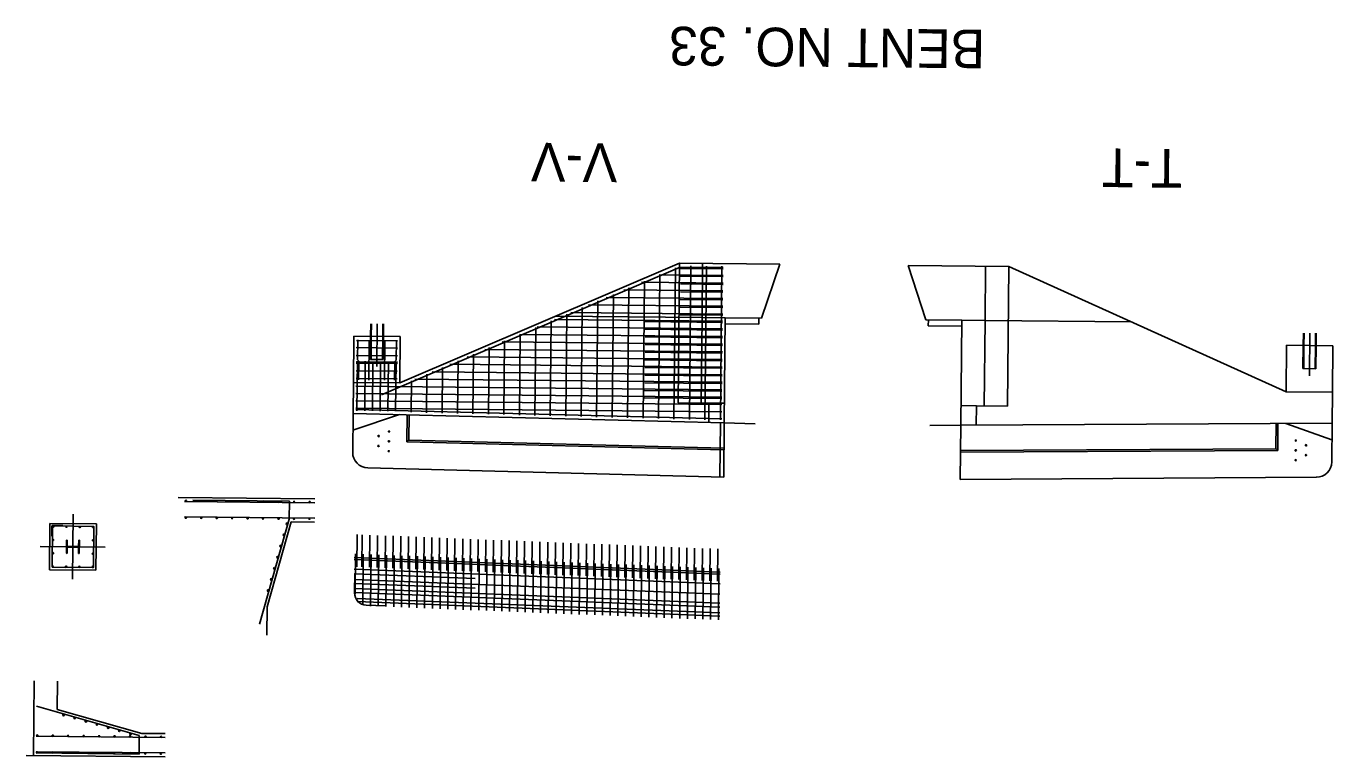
# Model space of a CAD drawing. Extents: x 631918 to 632319, y 373181 to 373282.
# Drawn here: x 632021.2 to 632105.7, y 373204.7 to 373251.9 of the extents above; entities that cross this region are included whole.
import ezdxf

# ---------------------------------------------------------------- set-up
doc = ezdxf.new("R2010")
doc.units = 0
for name, color, linetype in [('B_Boring', 7, 'Continuous'), ('BD-EXIST-OSB', 7, 'Continuous'), ('BD-LEGEND', 7, 'Continuous'), ('BD-PROP-COSS', 7, 'Continuous'), ('BD-REMOVE', 7, 'Continuous'), ('R_Border_Scale', 7, 'Continuous'), ('R_Road Edge of Travel', 7, 'Continuous'), ('R_Shade Removal', 7, 'Continuous'), ('R_Wall', 7, 'Continuous')]:
    doc.layers.add(name, color=color, linetype=linetype)

msp = doc.modelspace()

# ---------------------------------------------------------------- linework, layer by layer
at = {"layer": 'B_Boring'}
for p, q in [((632084.738, 373236.403), (632084.649, 373227.381)), ((632083.204, 373232.918), (632083.149, 373227.396)), ((632045.824, 373225.073), (632045.841, 373226.823)), ((632045.95, 373225.194), (632045.966, 373226.821)), ((632082.636, 373226.151), (632082.649, 373227.401)), ((632082.649, 373227.401), (632084.649, 373227.381)), ((632105.628, 373225.2), (632102.639, 373226.266)), ((632045.95, 373225.194), (632045.824, 373225.073)), ((632066.32, 373224.547), (632045.824, 373225.062)), ((632066.321, 373224.67), (632045.95, 373225.183))]:
    msp.add_line(p, q, dxfattribs=at)
at = {"layer": 'BD-EXIST-OSB'}
for p, q in [((632023.817, 373218.717), (632023.809, 373217.863)), ((632023.864, 373218.716), (632023.817, 373218.717)), ((632023.856, 373217.862), (632023.86, 373218.266)), ((632023.86, 373218.313), (632023.864, 373218.716)), ((632023.86, 373218.313), (632024.23, 373218.309)), ((632023.86, 373218.266), (632024.229, 373218.262)), ((632024.599, 373218.259), (632024.229, 373218.262)), ((632024.6, 373218.305), (632024.23, 373218.309)), ((632024.595, 373217.855), (632024.599, 373218.259)), ((632024.6, 373218.305), (632024.604, 373218.709)), ((632024.604, 373218.709), (632024.651, 373218.709)), ((632024.651, 373218.709), (632024.642, 373217.854)), ((632023.856, 373217.862), (632023.809, 373217.863)), ((632024.595, 373217.855), (632024.642, 373217.854))]:
    msp.add_line(p, q, dxfattribs=at)
at = {"layer": 'BD-LEGEND'}
for p, q in [((632039.871, 373221.38), (632031.026, 373221.468)), ((632036.79, 373214.411), (632038.345, 373219.895)), ((632039.856, 373219.88), (632038.345, 373219.895)), ((632022.715, 373216.801), (632022.745, 373219.801)), ((632025.744, 373219.771), (632022.745, 373219.801)), ((632025.744, 373219.771), (632025.715, 373216.771)), ((632025.715, 373216.771), (632022.715, 373216.801)), ((632036.79, 373214.411), (632036.772, 373212.58)), ((632021.723, 373209.619), (632021.675, 373204.789)), ((632023.205, 373207.774), (632023.223, 373209.604)), ((632023.205, 373207.774), (632028.689, 373206.219)), ((632030.201, 373206.204), (632028.689, 373206.219)), ((632030.186, 373204.704), (632021.204, 373204.793))]:
    msp.add_line(p, q, dxfattribs=at)
at = {"layer": 'BD-PROP-COSS'}
for p, q in [((632063.49, 373236.364), (632044.181, 373228.106)), ((632062.182, 373235.895), (632062.09, 373226.573)), ((632063.187, 373236.325), (632063.089, 373226.547)), ((632066.27, 373236.336), (632063.49, 373236.364)), ((632066.269, 373236.253), (632063.52, 373236.28)), ((632063.52, 373236.28), (632063.603, 373236.279)), ((632064.188, 373236.44), (632064.089, 373226.506)), ((632065.188, 373236.43), (632065.089, 373226.496)), ((632066.188, 373236.42), (632066.089, 373226.486)), ((632066.26, 373235.336), (632060.997, 373235.389)), ((632061.178, 373235.466), (632061.09, 373226.598)), ((632066.265, 373235.836), (632062.14, 373235.877)), ((632066.259, 373235.253), (632063.51, 373235.28)), ((632066.264, 373235.753), (632063.515, 373235.78)), ((632066.25, 373234.336), (632058.712, 373234.411)), ((632059.169, 373234.607), (632059.09, 373226.65)), ((632066.255, 373234.836), (632059.855, 373234.9)), ((632060.174, 373235.036), (632060.09, 373226.624)), ((632066.249, 373234.253), (632063.5, 373234.28)), ((632066.254, 373234.753), (632063.505, 373234.78)), ((632066.24, 373233.336), (632056.427, 373233.434)), ((632057.161, 373233.748), (632057.091, 373226.701)), ((632066.245, 373233.836), (632057.57, 373233.923)), ((632058.165, 373234.177), (632058.09, 373226.675)), ((632066.245, 373233.753), (632063.495, 373233.78)), ((632055.152, 373232.889), (632055.091, 373226.752)), ((632055.371, 373232.982), (632066.236, 373232.874)), ((632056.156, 373233.318), (632056.091, 373226.727)), ((632066.235, 373232.791), (632061.235, 373232.841)), ((632066.24, 373233.253), (632063.49, 373233.28)), ((632042.626, 373230.368), (632042.639, 373231.66)), ((632053.143, 373232.03), (632053.091, 373226.804)), ((632053.112, 373232.016), (632066.226, 373231.886)), ((632054.148, 373232.459), (632054.091, 373226.778)), ((632054.242, 373232.499), (632066.231, 373232.38)), ((632066.225, 373231.802), (632061.225, 373231.852)), ((632066.23, 373232.297), (632061.23, 373232.346)), ((632045.217, 373231.134), (632042.551, 373231.161)), ((632045.222, 373231.593), (632042.555, 373231.619)), ((632043.363, 373229.069), (632043.389, 373231.652)), ((632044.363, 373229.059), (632044.389, 373231.642)), ((632045.126, 373230.343), (632045.139, 373231.635)), ((632050.853, 373231.05), (632066.216, 373230.897)), ((632051.135, 373231.17), (632051.092, 373226.855)), ((632051.982, 373231.533), (632066.221, 373231.391)), ((632052.139, 373231.6), (632052.092, 373226.829)), ((632066.215, 373230.814), (632061.216, 373230.863)), ((632066.22, 373231.308), (632061.22, 373231.358)), ((632045.208, 373230.134), (632042.541, 373230.161)), ((632045.208, 373230.218), (632042.542, 373230.244)), ((632045.212, 373230.634), (632042.546, 373230.661)), ((632042.594, 373227.077), (632042.626, 373230.285)), ((632042.626, 373230.368), (632042.709, 373230.284)), ((632042.697, 373229.076), (632042.709, 373230.284)), ((632043.094, 373227.072), (632043.126, 373230.28)), ((632043.594, 373227.067), (632043.625, 373230.275)), ((632044.094, 373227.062), (632044.125, 373230.27)), ((632044.594, 373227.057), (632044.625, 373230.265)), ((632045.03, 373229.053), (632045.042, 373230.261)), ((632045.126, 373230.343), (632045.042, 373230.261)), ((632045.094, 373227.052), (632045.125, 373230.26)), ((632048.594, 373230.084), (632066.206, 373229.908)), ((632049.126, 373230.311), (632049.092, 373226.906)), ((632049.723, 373230.567), (632066.211, 373230.403)), ((632050.13, 373230.741), (632050.092, 373226.881)), ((632066.21, 373230.319), (632061.211, 373230.369)), ((632045.198, 373229.134), (632042.531, 373229.161)), ((632045.203, 373229.634), (632042.536, 373229.661)), ((632047.117, 373229.452), (632047.093, 373226.957)), ((632047.464, 373229.6), (632066.201, 373229.414)), ((632048.122, 373229.882), (632048.092, 373226.932)), ((632066.201, 373229.331), (632061.201, 373229.381)), ((632066.205, 373229.825), (632061.206, 373229.875)), ((632042.526, 373228.661), (632066.192, 373228.426)), ((632046.113, 373229.023), (632046.093, 373226.983)), ((632046.334, 373229.117), (632066.196, 373228.92)), ((632066.191, 373228.342), (632061.191, 373228.392)), ((632066.196, 373228.837), (632061.196, 373228.886)), ((632042.517, 373227.723), (632066.182, 373227.488)), ((632042.521, 373228.192), (632066.187, 373227.957)), ((632066.186, 373227.874), (632061.186, 373227.923)), ((632066.173, 373226.551), (632042.511, 373227.158)), ((632042.512, 373227.255), (632066.178, 373227.019)), ((632039.869, 373221.13), (632031.451, 373221.214)), ((632038.231, 373221.23), (632031.981, 373221.292)), ((632038.219, 373220.063), (632038.231, 373221.23)), ((632039.859, 373220.13), (632031.441, 373220.214)), ((632036.297, 373213.282), (632038.219, 373220.063)), ((632022.861, 373218.966), (632022.868, 373219.633)), ((632025.576, 373219.606), (632022.868, 373219.633)), ((632022.883, 373216.966), (632022.91, 373219.674)), ((632023.577, 373219.667), (632022.91, 373219.674)), ((632025.576, 373219.606), (632025.55, 373216.939)), ((632042.577, 373216.994), (632042.597, 373219.077)), ((632042.931, 373219.064), (632042.91, 373216.98)), ((632043.43, 373219.044), (632043.41, 373216.96)), ((632043.93, 373219.024), (632043.91, 373216.94)), ((632044.43, 373219.004), (632044.409, 373216.921)), ((632044.93, 373218.984), (632044.909, 373216.901)), ((632045.43, 373218.964), (632045.409, 373216.881)), ((632045.93, 373218.944), (632045.909, 373216.861)), ((632046.429, 373218.924), (632046.409, 373216.841)), ((632046.929, 373218.904), (632046.909, 373216.821)), ((632047.429, 373218.884), (632047.408, 373216.801)), ((632047.929, 373218.864), (632047.908, 373216.781)), ((632048.429, 373218.844), (632048.408, 373216.761)), ((632048.929, 373218.824), (632048.908, 373216.741)), ((632049.428, 373218.804), (632049.408, 373216.721)), ((632049.928, 373218.784), (632049.908, 373216.701)), ((632050.428, 373218.764), (632050.407, 373216.681)), ((632050.928, 373218.744), (632050.907, 373216.661)), ((632051.428, 373218.724), (632051.407, 373216.641)), ((632051.928, 373218.704), (632051.907, 373216.621)), ((632052.427, 373218.684), (632052.407, 373216.601)), ((632052.927, 373218.664), (632052.906, 373216.581)), ((632053.427, 373218.644), (632053.406, 373216.561)), ((632053.927, 373218.624), (632053.906, 373216.541)), ((632054.427, 373218.604), (632054.406, 373216.521)), ((632054.926, 373218.584), (632054.906, 373216.501)), ((632055.426, 373218.564), (632055.406, 373216.481)), ((632055.926, 373218.544), (632055.905, 373216.461)), ((632056.426, 373218.524), (632056.405, 373216.441)), ((632056.926, 373218.504), (632056.905, 373216.421)), ((632057.426, 373218.485), (632057.405, 373216.401)), ((632057.925, 373218.465), (632057.905, 373216.381)), ((632058.425, 373218.445), (632058.405, 373216.361)), ((632058.925, 373218.425), (632058.904, 373216.341)), ((632059.425, 373218.405), (632059.404, 373216.321)), ((632059.925, 373218.385), (632059.904, 373216.301)), ((632060.425, 373218.365), (632060.404, 373216.281)), ((632060.924, 373218.345), (632060.904, 373216.262)), ((632061.424, 373218.325), (632061.404, 373216.242)), ((632061.924, 373218.305), (632061.903, 373216.222)), ((632062.424, 373218.285), (632062.403, 373216.202)), ((632062.924, 373218.265), (632062.903, 373216.182)), ((632063.424, 373218.245), (632063.403, 373216.162)), ((632063.923, 373218.225), (632063.903, 373216.142)), ((632064.423, 373218.205), (632064.402, 373216.122)), ((632064.923, 373218.185), (632064.902, 373216.102)), ((632065.423, 373218.165), (632065.402, 373216.082)), ((632065.923, 373218.145), (632065.902, 373216.062)), ((632066.073, 373216.513), (632042.415, 373217.459)), ((632066.074, 373216.638), (632042.416, 373217.584)), ((632042.476, 373215.247), (632042.502, 373217.83)), ((632043.002, 373217.81), (632042.969, 373214.561)), ((632043.501, 373217.79), (632043.468, 373214.457)), ((632044.001, 373217.77), (632043.968, 373214.437)), ((632044.501, 373217.75), (632044.468, 373214.417)), ((632045.001, 373217.731), (632044.968, 373214.397)), ((632045.501, 373217.711), (632045.468, 373214.377)), ((632046, 373217.691), (632045.967, 373214.357)), ((632046.5, 373217.671), (632046.467, 373214.337)), ((632047, 373217.651), (632046.967, 373214.317)), ((632047.5, 373217.631), (632047.467, 373214.297)), ((632048, 373217.611), (632047.967, 373214.278)), ((632048.5, 373217.591), (632048.466, 373214.258)), ((632048.999, 373217.571), (632048.966, 373214.238)), ((632049.499, 373217.551), (632049.466, 373214.218)), ((632049.999, 373217.531), (632049.966, 373214.198)), ((632050.499, 373217.511), (632050.466, 373214.178)), ((632050.999, 373217.491), (632050.966, 373214.158)), ((632051.499, 373217.471), (632051.465, 373214.138)), ((632051.998, 373217.451), (632051.965, 373214.118)), ((632052.498, 373217.431), (632052.465, 373214.098)), ((632052.998, 373217.411), (632052.965, 373214.078)), ((632053.498, 373217.391), (632053.465, 373214.058)), ((632053.998, 373217.371), (632053.965, 373214.038)), ((632054.498, 373217.351), (632054.464, 373214.018)), ((632054.997, 373217.331), (632054.964, 373213.998)), ((632055.497, 373217.311), (632055.464, 373213.978)), ((632025.55, 373216.939), (632022.883, 373216.966)), ((632050.236, 373216.229), (632042.406, 373216.542)), ((632066.067, 373215.888), (632042.408, 373216.834)), ((632042.435, 373215.309), (632042.447, 373216.559)), ((632055.997, 373217.291), (632055.964, 373213.958)), ((632056.497, 373217.271), (632056.464, 373213.938)), ((632056.997, 373217.251), (632056.964, 373213.918)), ((632057.497, 373217.231), (632057.463, 373213.898)), ((632057.996, 373217.211), (632057.963, 373213.878)), ((632058.496, 373217.191), (632058.463, 373213.858)), ((632058.996, 373217.171), (632058.963, 373213.838)), ((632059.496, 373217.151), (632059.463, 373213.818)), ((632059.996, 373217.131), (632059.962, 373213.798)), ((632060.495, 373217.111), (632060.462, 373213.778)), ((632060.995, 373217.091), (632060.962, 373213.758)), ((632061.495, 373217.072), (632061.462, 373213.738)), ((632061.995, 373217.052), (632061.962, 373213.718)), ((632062.495, 373217.032), (632062.462, 373213.698)), ((632062.995, 373217.012), (632062.961, 373213.678)), ((632063.494, 373216.992), (632063.461, 373213.658)), ((632063.994, 373216.972), (632063.961, 373213.638)), ((632064.494, 373216.952), (632064.461, 373213.619)), ((632064.994, 373216.932), (632064.961, 373213.599)), ((632065.494, 373216.912), (632065.461, 373213.579)), ((632065.994, 373216.892), (632065.96, 373213.559)), ((632050.23, 373215.604), (632042.399, 373215.917)), ((632066.06, 373215.222), (632042.402, 373216.167)), ((632066.052, 373214.389), (632042.394, 373215.334)), ((632066.054, 373214.639), (632042.396, 373215.584)), ((632066.048, 373214.014), (632042.617, 373214.95)), ((632066.046, 373213.805), (632042.609, 373214.742)), ((632044.444, 373214.46), (632043.195, 373214.51)), ((632021.873, 373207.978), (632028.521, 373206.093)), ((632030.199, 373205.954), (632021.854, 373206.037)), ((632028.521, 373206.093), (632028.509, 373204.887)), ((632028.509, 373204.887), (632021.843, 373204.954)), ((632030.189, 373204.954), (632021.844, 373205.037))]:
    msp.add_line(p, q, dxfattribs=at)
for centre, radius in [((632031.535, 373221.255), 0.0417), ((632032.535, 373221.245), 0.0417), ((632033.535, 373221.235), 0.0417), ((632034.535, 373221.225), 0.0417), ((632035.535, 373221.215), 0.0417), ((632036.535, 373221.205), 0.0417), ((632037.535, 373221.195), 0.0417), ((632038.535, 373221.185), 0.0417), ((632039.535, 373221.175), 0.0417), ((632031.524, 373220.172), 0.0417), ((632032.524, 373220.162), 0.0417), ((632033.524, 373220.152), 0.0417), ((632034.524, 373220.142), 0.0417), ((632035.524, 373220.132), 0.0417), ((632036.524, 373220.122), 0.0417), ((632037.524, 373220.112), 0.0417), ((632038.524, 373220.102), 0.0417), ((632039.524, 373220.092), 0.0417), ((632022.951, 373219.59), 0.0417), ((632023.812, 373219.582), 0.0417), ((632024.673, 373219.573), 0.0417), ((632025.534, 373219.564), 0.0417), ((632037.875, 373219.052), 0.0556), ((632038.078, 373219.771), 0.0556), ((632022.942, 373218.729), 0.0417), ((632025.526, 373218.703), 0.0417), ((632037.671, 373218.333), 0.0556), ((632022.934, 373217.868), 0.0417), ((632025.517, 373217.842), 0.0417), ((632037.467, 373217.613), 0.0556), ((632022.925, 373217.007), 0.0417), ((632023.786, 373216.998), 0.0417), ((632024.647, 373216.99), 0.0417), ((632025.508, 373216.981), 0.0417), ((632037.263, 373216.894), 0.0556), ((632037.059, 373216.174), 0.0556), ((632036.855, 373215.455), 0.0556), ((632023.623, 373207.418), 0.0556), ((632024.345, 373207.214), 0.0556), ((632025.067, 373207.009), 0.0556), ((632025.789, 373206.805), 0.0556), ((632026.511, 373206.6), 0.0556), ((632027.233, 373206.395), 0.0556), ((632021.923, 373206.078), 0.0417), ((632022.923, 373206.068), 0.0417), ((632023.923, 373206.058), 0.0417), ((632024.923, 373206.048), 0.0417), ((632025.923, 373206.038), 0.0417), ((632026.923, 373206.028), 0.0417), ((632027.923, 373206.018), 0.0417), ((632027.955, 373206.191), 0.0556), ((632028.923, 373206.008), 0.0417), ((632029.923, 373205.998), 0.0417), ((632021.912, 373204.995), 0.0417), ((632022.912, 373204.985), 0.0417), ((632023.912, 373204.975), 0.0417), ((632024.912, 373204.965), 0.0417), ((632025.912, 373204.955), 0.0417), ((632026.912, 373204.945), 0.0417), ((632027.912, 373204.935), 0.0417), ((632028.912, 373204.925), 0.0417), ((632029.912, 373204.915), 0.0417)]:
    msp.add_circle(centre, radius, dxfattribs=at)
msp.add_arc((632043.227, 373215.301), 0.792, 179.43036, 267.712, dxfattribs=at)
at = {"layer": 'R_Border_Scale'}
for p, q in [((632064.905, 373233.1), (632064.939, 373236.599)), ((632083.204, 373232.918), (632083.239, 373236.418)), ((632064.905, 373233.1), (632055.442, 373233.194)), ((632066.405, 373233.085), (632064.905, 373233.1)), ((632081.704, 373232.933), (632083.204, 373232.918)), ((632083.204, 373232.918), (632092.667, 373232.824)), ((632065.35, 373227.573), (632066.35, 373227.563)), ((632066.337, 373226.297), (632042.342, 373226.913)), ((632082.649, 373227.401), (632081.649, 373227.411)), ((632081.636, 373226.145), (632105.639, 373226.283))]:
    msp.add_line(p, q, dxfattribs=at)
at = {"layer": 'R_Road Edge of Travel'}
for p, q in [((632043.475, 373231.902), (632043.483, 373232.705)), ((632043.522, 373231.901), (632043.53, 373232.705)), ((632044.261, 373231.894), (632044.269, 373232.697)), ((632044.308, 373231.893), (632044.316, 373232.697)), ((632043.46, 373230.402), (632043.475, 373231.902)), ((632043.507, 373230.401), (632043.522, 373231.901)), ((632044.246, 373230.394), (632044.261, 373231.894)), ((632044.293, 373230.393), (632044.308, 373231.893)), ((632103.772, 373231.302), (632103.78, 373232.106)), ((632103.819, 373231.302), (632103.827, 373232.105)), ((632104.558, 373231.294), (632104.566, 373232.098)), ((632104.605, 373231.294), (632104.613, 373232.097)), ((632103.757, 373229.802), (632103.772, 373231.302)), ((632103.804, 373229.802), (632103.819, 373231.302)), ((632104.544, 373229.794), (632104.558, 373231.294)), ((632104.59, 373229.794), (632104.605, 373231.294)), ((632043.46, 373230.402), (632044.293, 373230.393)), ((632104.59, 373229.794), (632103.757, 373229.802))]:
    msp.add_line(p, q, dxfattribs=at)
at = {"layer": 'R_Shade Removal'}
for p, q in [((632063.439, 373236.614), (632045.362, 373228.883)), ((632063.439, 373236.614), (632063.35, 373227.593)), ((632069.939, 373236.55), (632063.439, 373236.614)), ((632068.738, 373233.062), (632069.939, 373236.55)), ((632078.239, 373236.467), (632084.738, 373236.403)), ((632079.371, 373232.956), (632078.239, 373236.467)), ((632084.738, 373236.403), (632102.659, 373228.313)), ((632064.905, 373233.1), (632064.85, 373227.578)), ((632066.405, 373233.085), (632066.337, 373226.297)), ((632068.567, 373232.688), (632066.401, 373232.71)), ((632068.738, 373233.062), (632066.405, 373233.085)), ((632068.571, 373233.063), (632068.567, 373232.688)), ((632079.371, 373232.956), (632081.704, 373232.933)), ((632079.537, 373232.954), (632079.534, 373232.579)), ((632079.534, 373232.579), (632081.7, 373232.558)), ((632081.704, 373232.933), (632081.636, 373226.145)), ((632042.362, 373228.913), (632042.392, 373231.912)), ((632042.392, 373231.912), (632045.392, 373231.883)), ((632045.362, 373228.883), (632045.392, 373231.883)), ((632102.659, 373228.313), (632102.689, 373231.313)), ((632105.689, 373231.283), (632102.689, 373231.313)), ((632105.659, 373228.283), (632105.689, 373231.283)), ((632042.342, 373226.913), (632042.362, 373228.913)), ((632042.362, 373228.913), (632045.362, 373228.883)), ((632105.659, 373228.283), (632102.659, 373228.313)), ((632105.639, 373226.283), (632105.659, 373228.283)), ((632065.35, 373227.573), (632063.35, 373227.593)), ((632065.337, 373226.323), (632065.35, 373227.573)), ((632042.317, 373224.397), (632042.342, 373226.913)), ((632042.331, 373225.829), (632045.341, 373226.836)), ((632066.087, 373226.3), (632066.052, 373222.8)), ((632066.337, 373226.297), (632066.302, 373222.797)), ((632068.336, 373226.246), (632066.337, 373226.297)), ((632079.636, 373226.134), (632081.636, 373226.145)), ((632081.636, 373226.145), (632081.602, 373222.645)), ((632101.997, 373224.636), (632102.014, 373226.264)), ((632102.121, 373224.513), (632102.139, 373226.263)), ((632105.614, 373223.768), (632105.639, 373226.283)), ((632081.619, 373224.395), (632102.121, 373224.503)), ((632081.62, 373224.518), (632101.997, 373224.626)), ((632101.997, 373224.636), (632102.121, 373224.513)), ((632066.302, 373222.797), (632043.291, 373223.388)), ((632081.602, 373222.645), (632104.62, 373222.778))]:
    msp.add_line(p, q, dxfattribs=at)
for centre in [(632044.664, 373225.738), (632043.994, 373225.444), (632044.657, 373225.103), (632103.294, 373225.156), (632043.988, 373224.808), (632044.651, 373224.467), (632103.288, 373224.52), (632103.952, 373224.212), (632103.958, 373224.847), (632103.282, 373223.884)]:
    msp.add_circle(centre, 0.0417, dxfattribs=at)
for centre, start, end in [((632043.317, 373224.387), 179.43036, 268.53089), ((632104.614, 373223.778), 270.32983, 359.43036)]:
    msp.add_arc(centre, 1, start, end, dxfattribs=at)
at = {"layer": 'R_Wall'}
for p, q in [((632043.872, 373229.938), (632043.9, 373232.701)), ((632104.169, 373229.338), (632104.197, 373232.101)), ((632024.209, 373216.2), (632024.251, 373220.4)), ((632026.316, 373218.265), (632022.116, 373218.307))]:
    msp.add_line(p, q, dxfattribs=at)

# ---------------------------------------------------------------- texts
at = {"layer": 'BD-REMOVE'}
for s, p in [('BENT NO. 33', (632083.22, 373251.714)), ('V-V', (632059.435, 373244.358)), ('T-T', (632095.976, 373243.995))]:
    msp.add_text(s, height=2.5, rotation=179.43036, dxfattribs=at).set_placement(p)

doc.saveas('drawing.dxf')
